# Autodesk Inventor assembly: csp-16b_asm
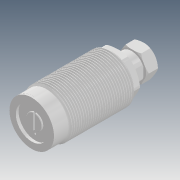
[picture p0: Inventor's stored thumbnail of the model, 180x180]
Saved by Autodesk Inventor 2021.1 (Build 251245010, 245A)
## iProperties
Created: 2019-04
Part Number: csp-16b_asm
Description: STEP AP214
Document SubType Name: Assembly
Designer: user
Title: csp-16b_asm.STEP
Revision Number: ÈÎºÎ
Sending System: SolidWorks 2016
Preprocessor: SwSTEP 2.0
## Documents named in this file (8)
- D:\Vault_2016\Projekty\Clamptek\Hydraulic\CSP-16\Inventor\CSP-16B\csp-16b_asm.iam
- D:\Vault_2016\Projekty\Clamptek\Hydraulic\CSP-16\Inventor\CSP-16B\CSP-16HG.ipt
- D:\Vault_2016\Projekty\Clamptek\Hydraulic\CSP-16\Inventor\CSP-16B\CSP-16DG.ipt
- D:\Vault_2016\Projekty\Clamptek\Hydraulic\CSP-16\Inventor\CSP-16B\M4X10_1.ipt
- D:\Vault_2016\Projekty\Clamptek\Hydraulic\CSP-16\Inventor\CSP-16B\CSP-16HSG_1.ipt
- D:\Vault_2016\Projekty\Clamptek\Hydraulic\CSP-16\Inventor\CSP-16B\CSP-16BT_1.ipt
- D:\Vault_2016\Projekty\Clamptek\Hydraulic\CSP-16\Inventor\CSP-16B\CSP-16LS_1.ipt
- D:\Vault_2016\Projekty\Clamptek\Hydraulic\CSP-16\Inventor\CSP-16B\CP-16DP_1.ipt
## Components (7 placed, 7 different names)
1. CSP-16HG_1
2. CSP-16DG_2
3. M4X10_1_3
4. CSP-16HSG_1_4
5. CSP-16BT_1_5
6. CSP-16LS_1_6
7. CP-16DP_1_7
